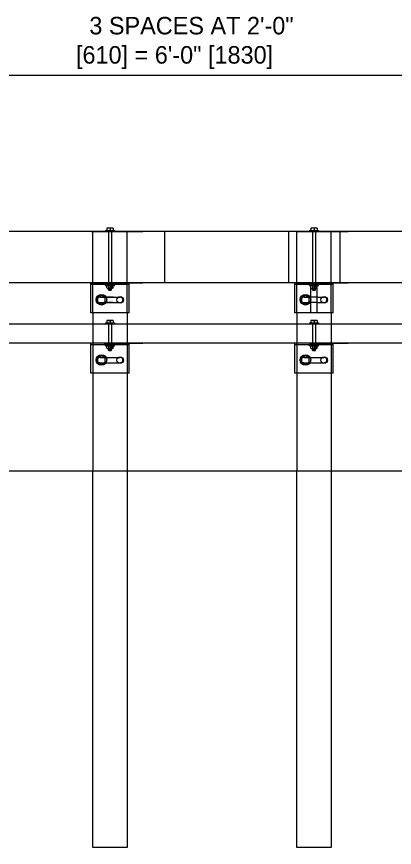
# Model space of a CAD drawing. Extents: x 49983 to 50021, y 49963.5 to 50011.4.
# Drawn here: x 50005.814 to 50007.107, y 49993.178 to 49996.022 of the extents above; entities that cross this region are included whole.
import ezdxf

# ---------------------------------------------------------------- set-up
doc = ezdxf.new("R2010")
doc.units = 0
for name, color, linetype in [('Level 1', 7, 'Continuous'), ('Level 10', 7, 'Continuous'), ('Level 2', 7, 'Continuous'), ('Level 3', 7, 'Continuous'), ('Level 4', 7, 'Continuous')]:
    doc.layers.add(name, color=color, linetype=linetype)

msp = doc.modelspace()

# ---------------------------------------------------------------- linework, layer by layer
at = {"layer": 'Level 1'}
for p, q in [((50013.5013, 49995.2862), (50005.468, 49995.2862)), ((50006.0709, 49995.2862), (50006.2466, 49995.2862)), ((50006.2164, 49995.2862), (50006.1012, 49995.2862)), ((50006.1181, 49995.2899), (50006.1493, 49995.2899)), ((50006.1181, 49995.2899), (50006.1181, 49995.2862)), ((50006.1228, 49995.2981), (50006.1228, 49995.2899)), ((50006.1283, 49995.2988), (50006.1393, 49995.2988)), ((50006.1338, 49995.2981), (50006.1338, 49995.2899)), ((50006.1448, 49995.2981), (50006.1448, 49995.2899)), ((50006.1493, 49995.2899), (50006.1493, 49995.2862)), ((50006.7737, 49995.2862), (50006.9494, 49995.2862)), ((50006.9192, 49995.2862), (50006.8039, 49995.2862)), ((50006.8166, 49995.2899), (50006.8478, 49995.2899)), ((50006.8166, 49995.2899), (50006.8166, 49995.2862)), ((50006.8213, 49995.2981), (50006.8213, 49995.2899)), ((50006.8268, 49995.2988), (50006.8378, 49995.2988)), ((50006.8323, 49995.2981), (50006.8323, 49995.2899)), ((50006.8433, 49995.2981), (50006.8433, 49995.2899)), ((50006.8478, 49995.2899), (50006.8478, 49995.2862)), ((50013.5013, 49995.1105), (50005.468, 49995.1105)), ((50006.068, 49995.008), (50006.068, 49995.1105)), ((50006.0709, 49995.1105), (50006.2466, 49995.1105)), ((50006.1149, 49995.1105), (50006.2466, 49995.1105)), ((50006.1997, 49995.008), (50006.1997, 49995.1105)), ((50006.7664, 49995.008), (50006.7664, 49995.1105)), ((50006.7737, 49995.1105), (50006.9494, 49995.1105)), ((50006.8176, 49995.1105), (50006.9494, 49995.1105)), ((50006.8982, 49995.008), (50006.8982, 49995.1105)), ((50006.1997, 49995.105), (50006.068, 49995.105)), ((50006.118, 49995.1014), (50006.118, 49995.1051)), ((50006.118, 49995.1014), (50006.1495, 49995.1014)), ((50006.1228, 49995.0942), (50006.1228, 49995.0997)), ((50006.1229, 49995.1014), (50006.1229, 49995.0998)), ((50006.1283, 49995.0925), (50006.1394, 49995.0925)), ((50006.1287, 49995.0864), (50006.1287, 49995.0925)), ((50006.139, 49995.0864), (50006.1287, 49995.0864)), ((50006.1287, 49995.0864), (50006.1298, 49995.0853)), ((50006.1298, 49995.0853), (50006.138, 49995.0853)), ((50006.1302, 49995.091), (50006.1375, 49995.091)), ((50006.1302, 49995.09), (50006.1375, 49995.09)), ((50006.1302, 49995.089), (50006.1375, 49995.089)), ((50006.1302, 49995.0879), (50006.1375, 49995.0879)), ((50006.1339, 49995.0997), (50006.1339, 49995.0942)), ((50006.139, 49995.0864), (50006.138, 49995.0853)), ((50006.139, 49995.0864), (50006.139, 49995.0925)), ((50006.1448, 49995.1014), (50006.1448, 49995.0998)), ((50006.145, 49995.0942), (50006.145, 49995.0997)), ((50006.1495, 49995.1014), (50006.1495, 49995.1051)), ((50006.8982, 49995.105), (50006.7664, 49995.105)), ((50006.8165, 49995.1014), (50006.8165, 49995.1051)), ((50006.8165, 49995.1014), (50006.8479, 49995.1014)), ((50006.8212, 49995.0942), (50006.8212, 49995.0997)), ((50006.8213, 49995.1014), (50006.8213, 49995.0998)), ((50006.8213, 49995.008), (50006.8213, 49995.0941)), ((50006.8268, 49995.0925), (50006.8379, 49995.0925)), ((50006.8272, 49995.0864), (50006.8272, 49995.0925)), ((50006.8374, 49995.0864), (50006.8272, 49995.0864)), ((50006.8272, 49995.0864), (50006.8282, 49995.0853)), ((50006.8282, 49995.0853), (50006.8364, 49995.0853)), ((50006.8287, 49995.091), (50006.8359, 49995.091)), ((50006.8287, 49995.09), (50006.8359, 49995.09)), ((50006.8287, 49995.089), (50006.8359, 49995.089)), ((50006.8287, 49995.0879), (50006.8359, 49995.0879)), ((50006.8323, 49995.0997), (50006.8323, 49995.0942)), ((50006.8374, 49995.0864), (50006.8364, 49995.0853)), ((50006.8374, 49995.0864), (50006.8374, 49995.0925)), ((50006.8433, 49995.1014), (50006.8433, 49995.0998)), ((50006.8433, 49995.008), (50006.8433, 49995.0941)), ((50006.8434, 49995.0942), (50006.8434, 49995.0997)), ((50006.8479, 49995.1014), (50006.8479, 49995.1051)), ((50006.1043, 49995.0678), (50006.0911, 49995.0601)), ((50006.0911, 49995.0601), (50006.0911, 49995.0453)), ((50006.1174, 49995.0601), (50006.1043, 49995.0678)), ((50006.1174, 49995.0453), (50006.1174, 49995.0601)), ((50006.1202, 49995.062), (50006.1681, 49995.062)), ((50006.8027, 49995.0678), (50006.7896, 49995.0601)), ((50006.7896, 49995.0601), (50006.7896, 49995.0453)), ((50006.8158, 49995.0601), (50006.8027, 49995.0678)), ((50006.8158, 49995.0453), (50006.8158, 49995.0601)), ((50006.8186, 49995.062), (50006.8213, 49995.062)), ((50006.8433, 49995.062), (50006.8665, 49995.062)), ((50006.0911, 49995.0453), (50006.1043, 49995.0382)), ((50006.1043, 49995.0382), (50006.1174, 49995.0453)), ((50006.1198, 49995.0437), (50006.1686, 49995.0437)), ((50006.7896, 49995.0453), (50006.8027, 49995.0382)), ((50006.8027, 49995.0382), (50006.8158, 49995.0453)), ((50006.8183, 49995.0437), (50006.8213, 49995.0437)), ((50006.8433, 49995.0437), (50006.8671, 49995.0437)), ((50006.1997, 49995.008), (50006.068, 49995.008)), ((50006.0751, 49995.008), (50006.0751, 49994.9698)), ((50006.1922, 49995.008), (50006.1922, 49994.9698)), ((50006.8982, 49995.008), (50006.7664, 49995.008)), ((50006.7736, 49995.008), (50006.7736, 49994.9698)), ((50006.8907, 49995.008), (50006.8907, 49994.9698)), ((50010.2874, 49994.9698), (50004.5699, 49994.9698)), ((50006.1181, 49994.9734), (50006.1493, 49994.9734)), ((50006.1181, 49994.9734), (50006.1181, 49994.9698)), ((50006.1228, 49994.9817), (50006.1228, 49994.9734)), ((50006.1283, 49994.9823), (50006.1393, 49994.9823)), ((50006.1338, 49994.9817), (50006.1338, 49994.9734)), ((50006.1448, 49994.9817), (50006.1448, 49994.9734)), ((50006.1493, 49994.9734), (50006.1493, 49994.9698)), ((50006.8166, 49994.9734), (50006.8478, 49994.9734)), ((50006.8166, 49994.9734), (50006.8166, 49994.9698)), ((50006.8213, 49994.9817), (50006.8213, 49994.9734)), ((50006.8268, 49994.9823), (50006.8378, 49994.9823)), ((50006.8323, 49994.9817), (50006.8323, 49994.9734)), ((50006.8433, 49994.9817), (50006.8433, 49994.9734)), ((50006.8478, 49994.9734), (50006.8478, 49994.9698)), ((50010.287, 49994.9041), (50005.1444, 49994.9041)), ((50006.068, 49994.8016), (50006.068, 49994.9041)), ((50006.1997, 49994.8986), (50006.068, 49994.8986)), ((50006.2246, 49994.9041), (50006.0928, 49994.9041)), ((50006.1143, 49994.9041), (50006.2461, 49994.9041)), ((50006.118, 49994.8949), (50006.118, 49994.8986)), ((50006.118, 49994.8949), (50006.1495, 49994.8949)), ((50006.1228, 49994.8876), (50006.1228, 49994.8932)), ((50006.1283, 49994.8859), (50006.1394, 49994.8859)), ((50006.1287, 49994.8798), (50006.1287, 49994.8859)), ((50006.1302, 49994.8845), (50006.1375, 49994.8845)), ((50006.1302, 49994.8835), (50006.1375, 49994.8835)), ((50006.1302, 49994.8824), (50006.1375, 49994.8824)), ((50006.1302, 49994.8814), (50006.1375, 49994.8814)), ((50006.1339, 49994.8932), (50006.1339, 49994.8876)), ((50006.139, 49994.8798), (50006.139, 49994.8859)), ((50006.145, 49994.8876), (50006.145, 49994.8932)), ((50006.1495, 49994.8949), (50006.1495, 49994.8986)), ((50006.1997, 49994.8016), (50006.1997, 49994.9041)), ((50006.7664, 49994.8016), (50006.7664, 49994.9041)), ((50006.8982, 49994.8986), (50006.7664, 49994.8986)), ((50006.9489, 49994.9041), (50006.7732, 49994.9041)), ((50006.8165, 49994.8949), (50006.8165, 49994.8986)), ((50006.8165, 49994.8949), (50006.8479, 49994.8949)), ((50006.8171, 49994.9041), (50006.9489, 49994.9041)), ((50006.8212, 49994.8876), (50006.8212, 49994.8932)), ((50006.8268, 49994.8859), (50006.8379, 49994.8859)), ((50006.8272, 49994.8798), (50006.8272, 49994.8859)), ((50006.8287, 49994.8845), (50006.8359, 49994.8845)), ((50006.8287, 49994.8835), (50006.8359, 49994.8835)), ((50006.8287, 49994.8824), (50006.8359, 49994.8824)), ((50006.8287, 49994.8814), (50006.8359, 49994.8814)), ((50006.8323, 49994.8932), (50006.8323, 49994.8876)), ((50006.8374, 49994.8798), (50006.8374, 49994.8859)), ((50006.8434, 49994.8876), (50006.8434, 49994.8932)), ((50006.8479, 49994.8949), (50006.8479, 49994.8986)), ((50006.8982, 49994.8016), (50006.8982, 49994.9041)), ((50006.1043, 49994.8613), (50006.0911, 49994.8537)), ((50006.0911, 49994.8537), (50006.0911, 49994.8389)), ((50006.1174, 49994.8537), (50006.1043, 49994.8613)), ((50006.1174, 49994.8389), (50006.1174, 49994.8537)), ((50006.1202, 49994.8555), (50006.1681, 49994.8555)), ((50006.139, 49994.8798), (50006.1287, 49994.8798)), ((50006.1287, 49994.8798), (50006.1298, 49994.8788)), ((50006.1298, 49994.8788), (50006.138, 49994.8788)), ((50006.139, 49994.8798), (50006.138, 49994.8788)), ((50006.8027, 49994.8613), (50006.7896, 49994.8537)), ((50006.7896, 49994.8537), (50006.7896, 49994.8389)), ((50006.8158, 49994.8537), (50006.8027, 49994.8613)), ((50006.8158, 49994.8389), (50006.8158, 49994.8537)), ((50006.8186, 49994.8555), (50006.8665, 49994.8555)), ((50006.8374, 49994.8798), (50006.8272, 49994.8798)), ((50006.8272, 49994.8798), (50006.8282, 49994.8788)), ((50006.8282, 49994.8788), (50006.8364, 49994.8788)), ((50006.8374, 49994.8798), (50006.8364, 49994.8788)), ((50006.0911, 49994.8389), (50006.1043, 49994.8318)), ((50006.1043, 49994.8318), (50006.1174, 49994.8389)), ((50006.1198, 49994.8372), (50006.1686, 49994.8372)), ((50006.7896, 49994.8389), (50006.8027, 49994.8318)), ((50006.8027, 49994.8318), (50006.8158, 49994.8389)), ((50006.8183, 49994.8372), (50006.8671, 49994.8372)), ((50006.1997, 49994.8016), (50006.068, 49994.8016)), ((50006.0751, 49994.8016), (50006.0751, 49994.4663)), ((50006.1922, 49994.8016), (50006.1922, 49994.4663)), ((50006.8982, 49994.8016), (50006.7664, 49994.8016)), ((50006.7736, 49994.8016), (50006.7736, 49994.4663)), ((50006.8907, 49994.8016), (50006.8907, 49994.4663)), ((50015.1755, 49994.4663), (50005.1046, 49994.4663))]:
    msp.add_line(p, q, dxfattribs=at)
for centre in [(50006.1044, 49995.0531), (50006.8028, 49995.0531), (50006.1044, 49994.8467), (50006.8028, 49994.8467)]:
    msp.add_circle(centre, 0.0181, dxfattribs=at)
for centre, radius, start, end in [((50006.1283, 49995.2757), 0.0231, 76.2307, 103.7693), ((50006.1393, 49995.2757), 0.0231, 76.2307, 103.7693), ((50006.8268, 49995.2757), 0.0231, 76.2307, 103.7693), ((50006.8378, 49995.2757), 0.0231, 76.2307, 103.7693), ((50006.1283, 49995.0916), 0.00981, 55.616, 124.384), ((50006.1283, 49995.1023), 0.00981, 235.616, 304.384), ((50006.1394, 49995.0916), 0.00981, 55.616, 124.384), ((50006.1394, 49995.1023), 0.00981, 235.616, 304.384), ((50006.8268, 49995.0916), 0.00981, 55.616, 124.384), ((50006.8268, 49995.1023), 0.00981, 235.616, 304.384), ((50006.8379, 49995.0916), 0.00981, 55.616, 124.384), ((50006.8379, 49995.1023), 0.00981, 235.616, 304.384), ((50006.1686, 49995.0528), 0.00916, 270, 93.2408), ((50006.8671, 49995.0528), 0.00916, 270, 93.2408), ((50006.1283, 49994.9592), 0.0231, 76.2307, 103.7693), ((50006.1393, 49994.9592), 0.0231, 76.2307, 103.7693), ((50006.8268, 49994.9592), 0.0231, 76.2307, 103.7693), ((50006.8378, 49994.9592), 0.0231, 76.2307, 103.7693), ((50006.1283, 49994.8851), 0.00981, 55.616, 124.384), ((50006.1283, 49994.8957), 0.00981, 235.616, 304.384), ((50006.1394, 49994.8851), 0.00981, 55.616, 124.384), ((50006.1394, 49994.8957), 0.00981, 235.616, 304.384), ((50006.8268, 49994.8851), 0.00981, 55.616, 124.384), ((50006.8268, 49994.8957), 0.00981, 235.616, 304.384), ((50006.8379, 49994.8851), 0.00981, 55.616, 124.384), ((50006.8379, 49994.8957), 0.00981, 235.616, 304.384), ((50006.1686, 49994.8464), 0.00916, 270, 93.2408), ((50006.8671, 49994.8464), 0.00916, 270, 93.2408)]:
    msp.add_arc(centre, radius, start, end, dxfattribs=at)
at = {"layer": 'Level 10'}
for p, q in [((50006.0751, 49995.008), (50006.0751, 49995.2862)), ((50006.1287, 49995.2899), (50006.1287, 49995.0925)), ((50006.1389, 49995.2899), (50006.1389, 49995.0925)), ((50006.1922, 49995.008), (50006.1922, 49995.2862)), ((50006.7736, 49995.008), (50006.7736, 49995.2862)), ((50006.8272, 49995.2899), (50006.8272, 49995.0925)), ((50006.8374, 49995.2899), (50006.8374, 49995.0925)), ((50006.8907, 49995.008), (50006.8907, 49995.2862)), ((50006.1229, 49995.1014), (50006.1229, 49995.105)), ((50006.1448, 49995.1014), (50006.1448, 49995.105)), ((50006.8213, 49995.1014), (50006.8213, 49995.105)), ((50006.8433, 49995.1014), (50006.8433, 49995.105)), ((50006.0996, 49995.062), (50006.1202, 49995.062)), ((50006.1448, 49995.062), (50006.1229, 49995.062)), ((50006.798, 49995.062), (50006.8186, 49995.062)), ((50006.8433, 49995.062), (50006.8213, 49995.062)), ((50006.0991, 49995.0437), (50006.1198, 49995.0437)), ((50006.1448, 49995.0437), (50006.1229, 49995.0437)), ((50006.7975, 49995.0437), (50006.8183, 49995.0437)), ((50006.8433, 49995.0437), (50006.8213, 49995.0437)), ((50006.0751, 49994.9698), (50006.0751, 49994.8016)), ((50006.1287, 49994.9734), (50006.1287, 49994.8859)), ((50006.1389, 49994.9734), (50006.1389, 49994.8859)), ((50006.1922, 49994.9698), (50006.1922, 49994.8016)), ((50006.7736, 49994.9698), (50006.7736, 49994.8016)), ((50006.8272, 49994.9734), (50006.8272, 49994.8859)), ((50006.8374, 49994.9734), (50006.8374, 49994.8859)), ((50006.8907, 49994.9698), (50006.8907, 49994.8016)), ((50006.0996, 49994.8555), (50006.1202, 49994.8555)), ((50006.798, 49994.8555), (50006.8186, 49994.8555)), ((50006.0991, 49994.8372), (50006.1198, 49994.8372)), ((50006.7975, 49994.8372), (50006.8183, 49994.8372))]:
    msp.add_line(p, q, dxfattribs=at)
for centre in [(50006.1686, 49995.0528), (50006.8671, 49995.0528), (50006.1686, 49994.8464), (50006.8671, 49994.8464)]:
    msp.add_circle(centre, 0.011, dxfattribs=at)
for centre in [(50006.0991, 49995.0528), (50006.7975, 49995.0528), (50006.0991, 49994.8464), (50006.7975, 49994.8464)]:
    msp.add_arc(centre, 0.00916, 86.7592, 270, dxfattribs=at)
at = {"layer": 'Level 3'}
msp.add_line((50005.4304, 49995.8215), (50007.535, 49995.8215), dxfattribs=at)
at = {"layer": 'Level 4'}
for p, q in [((50006.3204, 49995.2862), (50006.3204, 49995.1105)), ((50006.7444, 49995.2862), (50006.7444, 49995.1105)), ((50006.9201, 49995.2862), (50006.9201, 49995.1105)), ((50006.0751, 49993.1779), (50006.0751, 49994.4663)), ((50006.1922, 49994.4663), (50006.1922, 49993.1779)), ((50006.7736, 49993.1779), (50006.7736, 49994.4663)), ((50006.8907, 49994.4663), (50006.8907, 49993.1779)), ((50006.1922, 49993.1779), (50006.0751, 49993.1779)), ((50006.8907, 49993.1779), (50006.7736, 49993.1779))]:
    msp.add_line(p, q, dxfattribs=at)

# ---------------------------------------------------------------- texts
at = {"layer": 'Level 2'}
for s, p in [('3 SPACES AT 2\'-0"', (50006.0631, 49995.9615)), ('[610] = 6\'-0" [1830]', (50006.0173, 49995.8615))]:
    msp.add_text(s, height=0.06, dxfattribs=at).set_placement(p)

doc.saveas('drawing.dxf')
